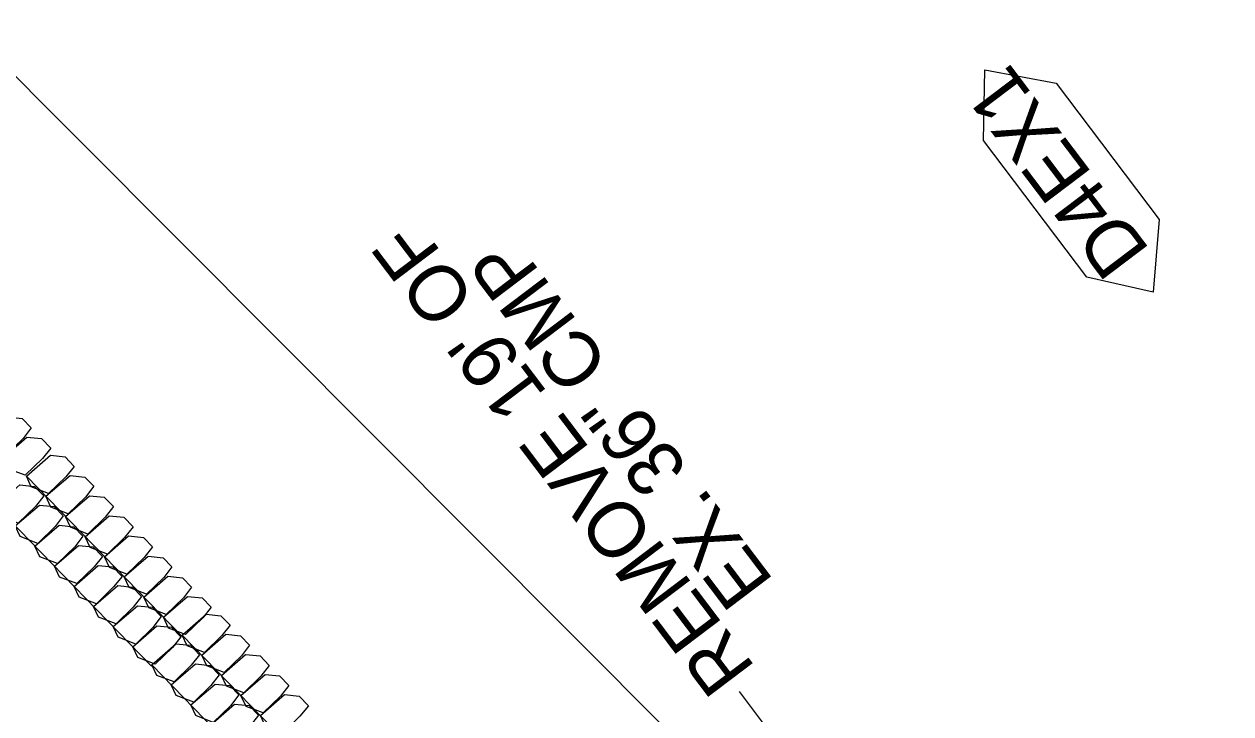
# Model space of a CAD drawing. Extents: x 465700 to 483515, y 488970 to 507540.
# Drawn here: x 476559 to 476667, y 500756 to 500817.8 of the extents above; entities that cross this region are included whole.
import ezdxf

# ---------------------------------------------------------------- set-up
doc = ezdxf.new("R2010")
doc.units = 0
for name, color, linetype in [('Exist Plan Preparation Watershed Blue', 7, 'Continuous'), ('Prop Drainage Structure Box Number Symbol CELL', 7, 'Continuous'), ('Prop Erosion Embankment Toe Protection CELL', 7, 'Continuous'), ('Prop Erosion Rip Rap Pad at Outlet Label', 7, 'Continuous')]:
    doc.layers.add(name, color=color, linetype=linetype)

msp = doc.modelspace()

# ---------------------------------------------------------------- linework, layer by layer
at = {"layer": 'Exist Plan Preparation Watershed Blue'}
for points in [[(476921.2, 501693.96), (476873.97, 501665.49), (476797.54, 501630.58), (476778.04, 501586.57), (476684.08, 501524.02), (476617.13, 501430.2), (476608.09, 501344.67), (476632.2, 501297.34), (476652.85, 501202.84), (476684.48, 501113.94), (476686.07, 501079.86), (476666.3, 501048.93), (476630.01, 501028.21), (476577.87, 501021.26), (476528.03, 501006.59), (476466.6, 500992.22), (476420.26, 500966.99), (476486.96, 500889.51), (476555.03, 500816.27), (476625.62, 500745.44), (476698.65, 500677.13), (476726.48, 500652.21), (476834.31, 500555.52), (476965.29, 500641)], [(476922.43, 500477.32), (476847.82, 500543.91), (476773.22, 500610.51), (476698.65, 500677.13), (476625.62, 500745.44), (476555.03, 500816.27), (476486.96, 500889.51), (476420.26, 500966.99), (476358.7, 501042.92), (476298.67, 501122.89), (476241.47, 501204.91)], [(476965.29, 500641), (476834.31, 500555.52), (476726.48, 500652.21), (476625.62, 500745.44), (476555.03, 500816.27), (476486.96, 500889.51), (476420.26, 500966.99), (476358.7, 501042.92), (476298.67, 501122.89), (476241.47, 501204.91)]]:
    msp.add_lwpolyline(points, dxfattribs=at)
at = {"layer": 'Prop Drainage Structure Box Number Symbol CELL'}
msp.add_lwpolyline([(476654.08, 500795.15), (476644.83, 500807.36), (476644.95, 500813.71), (476651.32, 500812.51), (476660.56, 500800.3), (476660.02, 500793.8), (476654.08, 500795.15)], dxfattribs=at)
at = {"layer": 'Prop Erosion Embankment Toe Protection CELL'}
for p, q in [((476559.16, 500777.31), (476573.09, 500762.96)), ((476556.43, 500774.66), (476570.37, 500760.32)), ((476573.11, 500763.09), (476587.04, 500748.74)), ((476570.38, 500760.44), (476584.32, 500746.1))]:
    msp.add_line(p, q, dxfattribs=at)
for points in [[(476559.59, 500781.65), (476558.86, 500780.69), (476557.31, 500779.19), (476555.75, 500779.79), (476555.3, 500780.76), (476557.47, 500782.62), (476558.78, 500782.49), (476559.59, 500781.65)], [(476561.35, 500779.84), (476560.6, 500778.89), (476559.06, 500777.4), (476557.51, 500777.98), (476557.06, 500778.94), (476559.21, 500780.82), (476560.52, 500780.7), (476561.35, 500779.84)], [(476563.45, 500778.2), (476562.69, 500777.26), (476561.15, 500775.76), (476559.6, 500776.35), (476559.16, 500777.31), (476561.31, 500779.19), (476562.63, 500779.04), (476563.45, 500778.2)], [(476565.19, 500776.41), (476564.45, 500775.45), (476562.91, 500773.95), (476561.35, 500774.55), (476560.9, 500775.52), (476563.07, 500777.38), (476564.39, 500777.23), (476565.19, 500776.41)], [(476560.72, 500775.55), (476559.97, 500774.61), (476558.42, 500773.11), (476556.88, 500773.7), (476556.43, 500774.66), (476558.58, 500776.54), (476559.9, 500776.4), (476560.72, 500775.55)], [(476566.95, 500774.6), (476566.21, 500773.64), (476564.67, 500772.14), (476563.1, 500772.74), (476562.66, 500773.7), (476564.82, 500775.57), (476566.13, 500775.44), (476566.95, 500774.6)], [(476562.46, 500773.76), (476561.73, 500772.8), (476560.18, 500771.3), (476558.62, 500771.91), (476558.17, 500772.87), (476560.34, 500774.73), (476561.66, 500774.59), (476562.46, 500773.76)], [(476568.71, 500772.79), (476567.95, 500771.84), (476566.41, 500770.34), (476564.86, 500770.93), (476564.42, 500771.89), (476566.57, 500773.77), (476567.87, 500773.65), (476568.71, 500772.79)], [(476564.22, 500771.95), (476563.49, 500770.99), (476561.94, 500769.49), (476560.38, 500770.1), (476559.93, 500771.06), (476562.1, 500772.92), (476563.41, 500772.79), (476564.22, 500771.95)], [(476570.45, 500770.99), (476569.69, 500770.05), (476568.15, 500768.55), (476566.61, 500769.14), (476566.16, 500770.1), (476568.31, 500771.98), (476569.63, 500771.84), (476570.45, 500770.99)], [(476565.98, 500770.14), (476565.23, 500769.19), (476563.68, 500767.7), (476562.14, 500768.28), (476561.69, 500769.25), (476563.84, 500771.12), (476565.15, 500771), (476565.98, 500770.14)], [(476572.19, 500769.2), (476571.45, 500768.24), (476569.91, 500766.74), (476568.35, 500767.35), (476567.9, 500768.31), (476570.07, 500770.17), (476571.39, 500770.02), (476572.19, 500769.2)], [(476567.73, 500768.34), (476566.97, 500767.4), (476565.43, 500765.9), (476563.88, 500766.49), (476563.43, 500767.45), (476565.58, 500769.33), (476566.91, 500769.19), (476567.73, 500768.34)], [(476573.95, 500767.39), (476573.21, 500766.43), (476571.67, 500764.93), (476570.11, 500765.53), (476569.66, 500766.5), (476571.83, 500768.36), (476573.13, 500768.23), (476573.95, 500767.39)], [(476569.47, 500766.55), (476568.73, 500765.59), (476567.19, 500764.09), (476565.62, 500764.7), (476565.18, 500765.66), (476567.34, 500767.52), (476568.67, 500767.38), (476569.47, 500766.55)], [(476575.71, 500765.58), (476574.96, 500764.63), (476573.41, 500763.14), (476571.87, 500763.72), (476571.42, 500764.68), (476573.57, 500766.56), (476574.88, 500766.44), (476575.71, 500765.58)], [(476571.23, 500764.74), (476570.49, 500763.78), (476568.95, 500762.28), (476567.38, 500762.89), (476566.93, 500763.85), (476569.1, 500765.71), (476570.41, 500765.58), (476571.23, 500764.74)], [(476577.4, 500763.98), (476576.64, 500763.04), (476575.1, 500761.54), (476573.56, 500762.13), (476573.11, 500763.09), (476575.26, 500764.97), (476576.58, 500764.82), (476577.4, 500763.98)], [(476572.99, 500762.93), (476572.23, 500761.99), (476570.69, 500760.49), (476569.14, 500761.08), (476568.69, 500762.04), (476570.84, 500763.92), (476572.15, 500763.79), (476572.99, 500762.93)], [(476574.67, 500761.33), (476573.92, 500760.39), (476572.38, 500758.89), (476570.83, 500759.48), (476570.38, 500760.44), (476572.53, 500762.32), (476573.86, 500762.18), (476574.67, 500761.33)], [(476579.14, 500762.19), (476578.4, 500761.23), (476576.86, 500759.73), (476575.3, 500760.33), (476574.85, 500761.3), (476577.02, 500763.16), (476578.34, 500763.01), (476579.14, 500762.19)], [(476580.9, 500760.38), (476580.16, 500759.42), (476578.62, 500757.92), (476577.06, 500758.52), (476576.61, 500759.48), (476578.78, 500761.35), (476580.08, 500761.22), (476580.9, 500760.38)], [(476576.42, 500759.54), (476575.68, 500758.58), (476574.14, 500757.08), (476572.57, 500757.69), (476572.13, 500758.65), (476574.29, 500760.51), (476575.62, 500760.37), (476576.42, 500759.54)], [(476582.66, 500758.57), (476581.9, 500757.62), (476580.36, 500756.12), (476578.82, 500756.71), (476578.37, 500757.67), (476580.52, 500759.55), (476581.83, 500759.43), (476582.66, 500758.57)], [(476578.18, 500757.73), (476577.44, 500756.77), (476575.89, 500755.27), (476574.33, 500755.88), (476573.88, 500756.84), (476576.05, 500758.7), (476577.36, 500758.57), (476578.18, 500757.73)], [(476579.94, 500755.92), (476579.18, 500754.97), (476577.64, 500753.48), (476576.09, 500754.06), (476575.64, 500755.03), (476577.79, 500756.9), (476579.1, 500756.78), (476579.94, 500755.92)], [(476584.4, 500756.77), (476583.65, 500755.83), (476582.1, 500754.33), (476580.56, 500754.92), (476580.11, 500755.88), (476582.26, 500757.76), (476583.58, 500757.62), (476584.4, 500756.77)]]:
    msp.add_lwpolyline(points, dxfattribs=at)
at = {"layer": 'Prop Erosion Rip Rap Pad at Outlet Label'}
msp.add_lwpolyline([(476619.74, 500703.22), (476625.86, 500754.23), (476622.98, 500758.04)], dxfattribs=at)

# ---------------------------------------------------------------- texts
at = {"layer": 'Prop Drainage Structure Box Number Symbol CELL'}
msp.add_text('D4EX1', height=5, rotation=127.1208, dxfattribs=at).set_placement((476659.81, 500797.52))
at = {"layer": 'Prop Erosion Rip Rap Pad at Outlet Label'}
for s, p in [("REMOVE 19' OF ", (476624.5, 500760.14)), ('EX. 36" CMP', (476626.14, 500767.91))]:
    msp.add_text(s, height=5, rotation=127.1092, dxfattribs=at).set_placement(p)

doc.saveas('drawing.dxf')
